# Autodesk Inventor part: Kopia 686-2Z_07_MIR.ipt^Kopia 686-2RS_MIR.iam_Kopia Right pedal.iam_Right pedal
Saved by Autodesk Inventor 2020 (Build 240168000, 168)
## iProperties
Created: 2017-10
Part Number: Kopia 686-2Z_07_MIR.ipt^Kopia 686-2RS_MIR.iam_Kopia Right pedal.iam_Right pedal
Material: Ogólny
Document SubType Name: Modeling
Designer: Tomasz
Density: 1 g/cm^3
Appearance: Domyślna
Sending System: SolidWorks 2017
Last Author: Tomasz
Last Saved: 2017-10-01
Author: Tomasz
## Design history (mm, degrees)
